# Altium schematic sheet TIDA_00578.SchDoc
size A
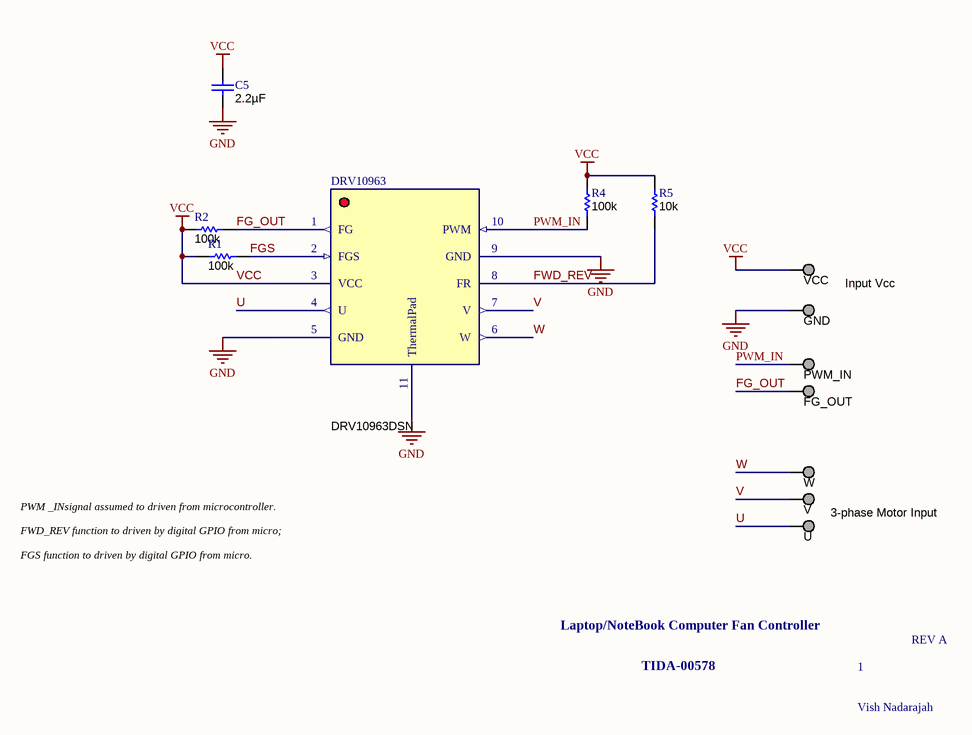
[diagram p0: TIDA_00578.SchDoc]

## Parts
C5  ValueDisplayed: 2.2µF  [0603L]  (hidden comment: C0603C225K8PACTU)
DRV10963  DRV10963DSN  [DSN with thermal vias]
FG_OUT  TESTPOINT  [TESTPOINT]  (value not drawn)  (no BOM)
GND  TESTPOINT  [TESTPOINT]  (value not drawn)  (no BOM)
PWM_IN  TESTPOINT  [TESTPOINT]  (value not drawn)  (no BOM)
R1  value 100k  [0402L]  (hidden comment: CRCW0402100KJNED)
R2  value 100k  [0402L]  (hidden comment: CRCW0402100KJNED)
R4  value 100k  [0402L]  (hidden comment: ERJ-2GE0R00X)
R5  value 10k  [0402L]  (hidden comment: CRCW040210K0JNED)
U  TESTPOINT  [TESTPOINT]  (value not drawn)  (no BOM)
V  TESTPOINT  [TESTPOINT]  (value not drawn)  (no BOM)
VCC  TESTPOINT  [TESTPOINT]  (value not drawn)  (no BOM)
W  TESTPOINT  [TESTPOINT]  (value not drawn)  (no BOM)

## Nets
GND: C5.2 DRV10963.5(GND) DRV10963.9(GND) DRV10963.11(ThermalPad) GND.1
VCC: C5.1 DRV10963.3(VCC) R1.2 R2.2 R4.1 R5.2 VCC.1
FG_OUT: DRV10963.1(FG) FG_OUT.1 R2.1
FGS: DRV10963.2(FGS) R1.1
FWD_REV: DRV10963.8(FR) R5.1
PWM_IN: DRV10963.10(PWM) PWM_IN.1 R4.2
U: DRV10963.4(U) U.1
V: DRV10963.7(V) V.1
W: DRV10963.6(W) W.1

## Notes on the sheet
- Input Vcc
- 3-phase Motor Input
- PWM _INsignal assumed to driven from microcontroller.
  FWD_REV function to driven by digital GPIO from micro;
  FGS function to driven by digital GPIO from micro.
- Laptop/NoteBook Computer Fan Controller
- TIDA-00578
- 1
- REV A
- Vish Nadarajah

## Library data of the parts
C5 = C0603C225K8PACTU: CAP, CERM, 2.2uF, 10V, +/-10%, X5R, 0603; Manufacturer: Kemet; Polarized: N; CompType: Capacitor; U/M: EA; Cap_F: 0.0000022; Tolerance_%: 10; Value1: Unknown; TaMin_C: -55; TaMax_C: 85; Cap_Case: 0603
DRV10963 = DRV10963BDSN: Manufacturer: Texas Instruments; SymbolCreator: a0271951; CompType: 10 pin QFN; U/M: GM
FG_OUT GND PWM_IN U V VCC W = TESTPOINT: TEST POINT.  No entry in BOM.
R1 R2 = CRCW0402100KJNED: RES, 100k ohm, 5%, 0.063W, 0402; Manufacturer: Vishay-Dale; CompType: Resistor; Res_ohm: 100000; Tolerance_%: 5; Power_W: 0.063; VDC_V: 50; TempCo: 200 ppm/C; EIA_Code: E24; U/M: EA
R4 = ERJ-2GE0R00X: RES, 0 ohm, 5%, 0.063W, 0402; Manufacturer: Panasonic; CompType: Resistor; Res_ohm: 0; Value_Code: 0000; Tolerance_%: 5; Power_W: 0.063; VDC_V: 50; TempCo: 600 ppm/C; EIA_Code: E24; U/M: EA
R5 = CRCW040210K0JNED: RES, 10k ohm, 5%, 0.063W, 0402; Manufacturer: Vishay-Dale; CompType: Resistor; Res_ohm: 10000; Value_Code: 10k0; Tolerance_%: 5; Power_W: 0.063; VDC_V: 50; TempCo: 200 ppm/C; EIA_Code: E24; U/M: EA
